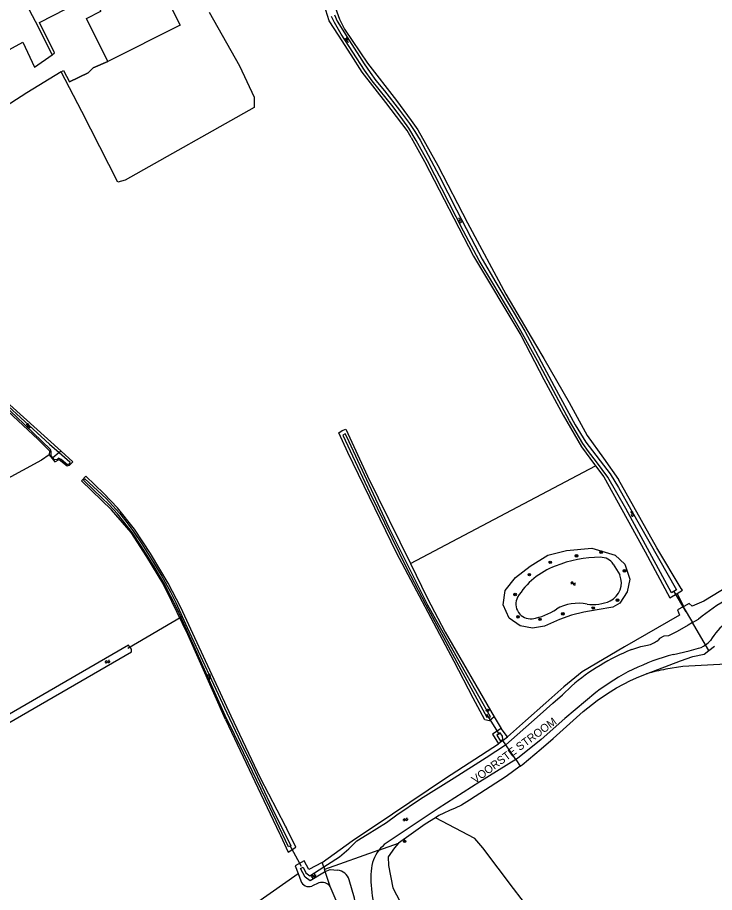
# Model space of a CAD drawing. Extents: x 135999 to 138000, y 396000 to 398501.
# Drawn here: x 136877 to 137094.8, y 396708.1 to 396981.4 of the extents above; entities that cross this region are included whole.
import ezdxf

# ---------------------------------------------------------------- set-up
doc = ezdxf.new("R2010")
doc.units = 0
for name, color, linetype in [('gg-afsc-lijn draadraster', 7, 'Continuous'), ('gg-afsc-muur', 7, 'Continuous'), ('gg-anno-naam water', 7, 'Continuous'), ('gg-bbg-bijgebouw', 7, 'Continuous'), ('gg-knt-BGT kruinlijn', 7, 'Continuous'), ('gg-knt-bronhoudergrens', 7, 'Continuous'), ('gg-kntw-bovenkant insteek waterloop', 7, 'Continuous'), ('gg-kntw-waterlijn', 7, 'Continuous'), ('gg-kwrk-duiker nz buis', 7, 'Continuous'), ('gt-grn-groengrens', 7, 'Continuous'), ('gt-grn-vlakafsluiter', 7, 'Continuous'), ('gt-symb-boom', 7, 'Continuous'), ('gt-symb-watersymbool', 7, 'Continuous'), ('gx-grn-maaiveld', 7, 'Continuous')]:
    doc.layers.add(name, color=color, linetype=linetype)

# ---------------------------------------------------------------- blocks, each defined once
blk = doc.blocks.new('gt0-WA')
at = {"layer": 'gt-symb-watersymbool'}
for centre, start, end in [((-0.32, 0.02), 28.0725, 151.9275), ((0.43, 0.42), 208.0725, 331.9275), ((-0.32, -0.43), 28.0725, 151.9275), ((0.43, -0.03), 208.0725, 331.9275)]:
    blk.add_arc(centre, 0.425, start, end, dxfattribs=at)
blk = doc.blocks.new('gt0-BOOM')
at = {"layer": 'gt-symb-boom'}
for radius in [0.4, 0.2]:
    blk.add_circle((0, 0), radius, dxfattribs=at)

msp = doc.modelspace()

# ---------------------------------------------------------------- linework, layer by layer
at = {"layer": 'gg-afsc-lijn draadraster'}
msp.add_line((136883.71, 396978.2), (136862.33, 397018.93), dxfattribs=at)
at = {"layer": 'gg-afsc-muur'}
for points in [[(136883.88, 396979.86), (136900.29, 396988.38), (136903.04, 396983.36)], [(136905.27, 396967.71), (136900.68, 396965.73), (136899.04, 396964.11), (136893.21, 396961.29)]]:
    msp.add_lwpolyline(points, dxfattribs=at)
at = {"layer": 'gg-bbg-bijgebouw'}
for points in [[(136921.08, 396992.42), (136927.81, 396979.02), (136905.27, 396967.71)], [(136905.27, 396967.71), (136898.54, 396981.1), (136903.04, 396983.36)]]:
    msp.add_lwpolyline(points, dxfattribs=at)
at = {"layer": 'gg-knt-BGT kruinlijn'}
msp.add_lwpolyline([(137098.27, 396779.44), (137084.85, 396778.7), (137079.55, 396777.84)], dxfattribs=at)
msp.add_arc((137087.1, 396734.1), 44.39, 99.788, 107.7671, dxfattribs=at)
at = {"layer": 'gg-knt-bronhoudergrens'}
for p, q in [((137085.17, 396797.45), (137083.11, 396801.55)), ((137025.93, 396763.03), (137028.11, 396759.34)), ((136935.91, 396693.85), (136964.64, 396714.1))]:
    msp.add_line(p, q, dxfattribs=at)
msp.add_lwpolyline([(137042.66, 396813.49), (137048.53, 396814.95), (137056.41, 396815.62), (137063.71, 396813.53), (137066.79, 396810.63), (137068.29, 396806.01), (137067.49, 396802), (137065.22, 396798.53), (137062.95, 396797.2), (137058.14, 396796.4), (137053.91, 396795.66), (137050.11, 396794.76), (137046.3, 396793.4), (137041.67, 396791.31), (137037.95, 396790.67), (137034.05, 396791.4), (137030.6, 396793.85), (137028.7, 396798.02), (137029.31, 396802.41), (137032.64, 396806.54), (137037.18, 396810.01), (137042.66, 396813.49)], dxfattribs=at)
at = {"layer": 'gg-kntw-bovenkant insteek waterloop'}
for p, q in [((137057.31, 396841.77), (137057.58, 396841.41)), ((137057.58, 396841.41), (137060.14, 396837.98)), ((136897.01, 396836.68), (136898.4, 396838.16)), ((137084.73, 396802.52), (137084.37, 396803.11)), ((137080.77, 396800.15), (137083.11, 396801.55)), ((137083.11, 396801.55), (137084.73, 396802.52)), ((137086.89, 396798.42), (137085.17, 396797.45)), ((136941.99, 396762.13), (136953.03, 396738.86)), ((137028.11, 396759.34), (137025.39, 396757.62)), ((137030.07, 396756.7), (137028.11, 396759.34)), ((137025.39, 396757.62), (137027.26, 396754.54)), ((136953.03, 396738.86), (136958.88, 396726.6)), ((136958.88, 396726.6), (136959, 396726.35)), ((136961.19, 396728.04), (136961.07, 396728.29)), ((136963.98, 396722.24), (136961.19, 396728.04)), ((136961.52, 396720.76), (136963.98, 396722.24)), ((136966.53, 396717.97), (136963.77, 396716.43)), ((136963.77, 396716.43), (136964.64, 396714.1)), ((136964.64, 396714.1), (136965.5, 396711.77)), ((136971.17, 396711.11), (136968.95, 396710.12))]:
    msp.add_line(p, q, dxfattribs=at)
for points in [[(137000, 396949.24), (137002.11, 396946.35), (137008.33, 396935.2), (137017.63, 396917.31), (137029.58, 396894.99), (137038.84, 396879.29)], [(137000, 396943.89), (137004.18, 396936.44), (137019.43, 396906.91), (137034.24, 396882.21), (137041.47, 396868.4), (137047.5, 396857.24), (137053.17, 396847.33), (137057.31, 396841.77)], [(137038.84, 396879.29), (137041.42, 396874.91), (137049.34, 396861.13), (137054.93, 396850.82), (137060.06, 396843.8), (137064.81, 396837.1)], [(136864.99, 396866.77), (136875.55, 396856.99), (136883.5, 396849.62), (136887.04, 396846.03), (136886.91, 396844.82)], [(136977.42, 396851.68), (136978.39, 396852.44), (136979.53, 396852.82), (136986.39, 396838.17), (136999.8, 396810.85)], [(137019.4, 396768.84), (137013.38, 396780.26), (136995.44, 396814.21), (136980.24, 396845.59), (136977.42, 396851.68)], [(136888.65, 396842.61), (136890.06, 396843.37), (136892.51, 396841.36)], [(136892.51, 396841.36), (136893.25, 396841.56), (136894.32, 396842.66)], [(136941.99, 396762.13), (136930.19, 396788.66), (136925.25, 396799), (136922.41, 396804.69), (136917.44, 396812.98), (136912.54, 396820.53), (136906.39, 396827.62), (136897.01, 396836.68)], [(136943.79, 396763.16), (136931.75, 396789.01), (136927.98, 396797.11), (136924.06, 396804.77), (136918.52, 396813.99), (136913.59, 396821.57), (136908.29, 396828.23), (136903.99, 396832.71), (136898.4, 396838.16)], [(137060.14, 396837.98), (137073.15, 396814.56), (137080.77, 396800.15)], [(137084.37, 396803.11), (137076.71, 396815.81), (137064.81, 396837.1)], [(136999.8, 396810.85), (137005.03, 396800.19), (137010.65, 396789.47), (137025.93, 396763.03)], [(137102.07, 396805.56), (137091.45, 396799.13), (137087.78, 396797.54), (137086.89, 396798.42)], [(137083.22, 396796.36), (137083.87, 396794.77), (137066.64, 396784.83), (137053.38, 396777.05), (137047.73, 396772.4), (137042.11, 396767.41), (137035.75, 396761.71), (137030.07, 396756.7)], [(136731.41, 396678.55), (136822, 396730.93), (136912.6, 396783.32), (136912.62, 396784.12), (136911.68, 396785.34), (136820.87, 396732.81), (136730.07, 396680.27), (136730.6, 396679.35), (136731.41, 396678.55)], [(137025.93, 396763.03), (137024.49, 396761.69), (137022.98, 396762.07), (137019.4, 396768.84)], [(136961.07, 396728.29), (136960.78, 396728.89), (136952.96, 396743.86), (136943.79, 396763.16)], [(137011.95, 396733.7), (137010.15, 396732.9), (137008.65, 396732.13), (137007.55, 396731.44)], [(137007.55, 396731.44), (137004.4, 396729.48), (137000, 396726.32), (136995.99, 396723.48)], [(136959, 396726.35), (136959.19, 396725.95), (136961.52, 396720.76)], [(136995.99, 396723.48), (136994.8, 396722.05), (136992.85, 396719.25), (136992.93, 396716.57), (136994.31, 396709.6), (136999.87, 396698.88), (137000.79, 396691.21)], [(136975.69, 396674.93), (136977.46, 396676.87), (136978.93, 396681.13), (136978.86, 396694.34), (136976.85, 396704.9), (136974.7, 396710.03)]]:
    msp.add_lwpolyline(points, dxfattribs=at)
for centre, radius, start, end in [((136968.02, 396712.61), 2.66, 198.3459, 290.4131), ((136972.17, 396708.07), 3.2, 37.8692, 108.3403)]:
    msp.add_arc(centre, radius, start, end, dxfattribs=at)
at = {"layer": 'gg-kntw-waterlijn'}
for p, q in [((137063.14, 396810.66), (137065.18, 396807.3)), ((137026.71, 396757.29), (137027.89, 396755.34))]:
    msp.add_line(p, q, dxfattribs=at)
for points in [[(136978.66, 396850.95), (136987.06, 396833), (136998.57, 396809.51), (137004.59, 396797.92), (137014.26, 396780.09), (137023.61, 396762.86), (137024.77, 396763.03), (137017.47, 396775.92), (137005.24, 396797.84), (137000.56, 396807.2), (136993.16, 396822.01), (136979.85, 396850.42), (136979.38, 396851.43), (136978.66, 396850.95)], [(136961.72, 396722.35), (136955.8, 396734.7), (136947.75, 396751.51), (136941.91, 396763.39), (136927.07, 396796.34), (136922.68, 396804.88), (136919.66, 396809.99), (136915.56, 396816.48), (136912.89, 396820.46), (136908.24, 396826.36), (136905.65, 396829.16), (136900.86, 396833.8), (136897.62, 396836.93), (136898.02, 396837.35), (136904.66, 396831.15), (136908.83, 396826.56), (136911.54, 396823.17), (136913.28, 396820.83), (136915.82, 396817.06), (136919.51, 396811.16), (136922.12, 396806.93), (136924.83, 396802), (136926.49, 396798.66), (136930.05, 396790.86), (136942.45, 396764.2), (136946.73, 396755), (136950.39, 396747.54), (136956.46, 396734.67), (136962.38, 396722.74), (136961.72, 396722.35)], [(137068.91, 396783.99), (137071.72, 396784.94), (137073.85, 396785.35)], [(137081.98, 396782.47), (137086.85, 396783.65), (137089.02, 396784.18)], [(137027.89, 396755.34), (137028.64, 396756.05), (137028.57, 396756.98), (137027.83, 396758.03), (137026.71, 396757.29)], [(136982.28, 396681.64), (136982.57, 396686.06), (136983.08, 396701), (136982.28, 396706.39), (136980.66, 396712.05)]]:
    msp.add_lwpolyline(points, dxfattribs=at)
for centre, radius, start, end in [((137059.04, 396775.64), 37.18, 89.893, 112.1587), ((137059.23, 396808.19), 4.63, 32.276, 91.4773), ((137053.51, 396787.79), 23.85, 110.8677, 148.1946), ((137059.32, 396804.88), 6.35, 296.3827, 22.4557), ((137037.3, 396798.2), 4.6, 152.0701, 276.6221), ((137052.21, 396784.74), 13.72, 78.5395, 119.8696), ((137056.78, 396811.29), 13.23, 262.0091, 293.9011), ((137126.31, 396749.51), 57.19, 118.2588, 129.7064), ((137034.94, 396811.91), 18.5, 279.0091, 304.3578), ((137112.32, 396775.21), 22.13, 108.1738, 148.4196), ((137071.57, 396794.38), 9.31, 284.2017, 306.6843), ((137094.28, 396720.69), 68.2, 111.8367, 130.4359), ((137098.76, 396717.52), 67.08, 104.4828, 127.7198), ((136976.61, 396710.83), 4.23, 16.8248, 85.3676), ((137018.3, 396712.29), 30.9, 175.2981, 208.3557)]:
    msp.add_arc(centre, radius, start, end, dxfattribs=at)
at = {"layer": 'gg-kwrk-duiker nz buis'}
for p, q in [((137082.05, 396802.15), (137085.81, 396795.81)), ((136911.46, 396784.45), (136928.3, 396794.28)), ((137023.56, 396763.82), (137027.48, 396757.43)), ((136965.77, 396716.28), (136962.16, 396722.69))]:
    msp.add_line(p, q, dxfattribs=at)
at = {"layer": 'gt-grn-groengrens'}
msp.add_line((136999.8, 396810.85), (137057.58, 396841.41), dxfattribs=at)
msp.add_lwpolyline([(137012.5, 396666.03), (137044.67, 396690.76), (137043.15, 396693.73), (137039.16, 396699.99), (137031.95, 396709.34), (137022.35, 396722.07), (137019.89, 396725), (137007.55, 396731.44)], dxfattribs=at)
at = {"layer": 'gt-grn-vlakafsluiter'}
msp.add_lwpolyline([(136886.91, 396844.82), (136884.46, 396843.11), (136872.6, 396836.66)], dxfattribs=at)
at = {"layer": 'gx-grn-maaiveld'}
for p, q in [((136883.71, 396978.2), (136862.33, 397018.93)), ((136887.84, 396969.81), (136883.71, 396978.2)), ((136886.91, 396844.82), (136887.78, 396843.71)), ((136887.78, 396843.71), (136888.04, 396843.92)), ((136890.03, 396845.54), (136888.04, 396843.92)), ((136890.61, 396846), (136890.03, 396845.54)), ((136890.61, 396846), (136894.32, 396842.66)), ((136887.78, 396843.71), (136888.65, 396842.61)), ((137084.99, 396797.35), (137083.22, 396796.36)), ((137085.17, 396797.45), (137084.99, 396797.35)), ((137084.99, 396797.35), (137087.91, 396792.42)), ((137087.91, 396792.42), (137089.77, 396793.51)), ((137092, 396785.49), (137087.91, 396792.42)), ((137093.04, 396783.73), (137092, 396785.49)), ((137093.04, 396783.73), (137094.77, 396785.05)), ((137028.67, 396755.63), (137027.26, 396754.54)), ((137029.57, 396754.27), (137028.67, 396755.63)), ((137032.65, 396749.63), (137029.57, 396754.27)), ((137032.65, 396749.63), (137034.02, 396747.58)), ((136989.94, 396721.35), (136995.99, 396723.48)), ((136989.94, 396721.35), (136972.93, 396715.34)), ((136968.38, 396713.36), (136972.68, 396716.11)), ((136972.68, 396716.11), (136972.2, 396717.54)), ((136972.68, 396716.11), (136972.93, 396715.34)), ((136973.17, 396714.65), (136972.93, 396715.34)), ((136974.7, 396710.03), (136973.17, 396714.65))]:
    msp.add_line(p, q, dxfattribs=at)
for points in [[(137000, 396943.89), (136998.72, 396946.17), (136992.04, 396954.86), (136984.64, 396964.39), (136981.25, 396969.76), (136977.24, 396975.86), (136974.38, 396980.38), (136972.85, 396985.36), (136971.89, 396990.65), (136970.75, 396997.59), (136970.06, 397000)], [(136972.61, 397000), (136974.25, 396993.89), (136975.34, 396988.01), (136976.4, 396984.38), (136977.65, 396980.94), (136979.18, 396977.81), (136986.35, 396967.11), (136995.41, 396955.52), (137000, 396949.24)], [(136887.84, 396969.81), (136888.6, 396970.35), (136883.88, 396979.86), (136900.29, 396988.38), (136903.04, 396983.36)], [(136936.85, 396983.11), (136946.39, 396966.31), (136950.91, 396956.5), (136950.94, 396953.26), (136910.62, 396930.6), (136908.33, 396930), (136897.08, 396952.02), (136890.62, 396964.4)], [(137081.28, 396801.7), (137067.1, 396828.01), (137061.46, 396837.89), (137057.9, 396842.63), (137055.45, 396845.91), (137053.62, 396848.35), (137049.41, 396855.48), (137039.44, 396874.21), (137034.28, 396883.6), (137031.4, 396888.4), (137025.52, 396898.44), (137021.22, 396905.53), (137016.39, 396914.72), (137005.08, 396936.63), (137001.59, 396943.04), (136999.3, 396946.82), (136997.34, 396949.48), (136994.4, 396953.48), (136987.86, 396961.64), (136985.43, 396964.97), (136978.16, 396976.23), (136976, 396979.86), (136975.11, 396981.77)], [(136976.04, 396982.28), (136976.91, 396980.31), (136980.75, 396974.11), (136985.32, 396966.91), (136987.15, 396964.24), (136988.94, 396961.77), (136991.62, 396958.47), (136996.33, 396952.51), (136999.44, 396948.36), (137001.15, 396945.83), (137002.8, 396943.07), (137008.79, 396931.92), (137014.2, 396921.36), (137018.77, 396912.46), (137022.14, 396905.9), (137026.43, 396898.65), (137031.82, 396889.56), (137035.47, 396883.4), (137037.86, 396878.94), (137040.58, 396873.84), (137044.64, 396866.23), (137051.27, 396854.21), (137054.59, 396848.81), (137062.12, 396838.92), (137064.72, 396834.62), (137068.62, 396827.7), (137082.92, 396802.66), (137081.28, 396801.7)], [(136858.3, 396962.57), (136878.62, 396973.67), (136882.31, 396965.86), (136887.84, 396969.81)], [(136890.62, 396964.4), (136891.39, 396964.87), (136893.21, 396961.29), (136899.04, 396964.11), (136900.68, 396965.73), (136905.27, 396967.71)], [(136890.62, 396964.4), (136879.87, 396957.84), (136865.13, 396948.46), (136864.32, 396949.25)], [(136888.04, 396843.92), (136887.55, 396844.48), (136887.55, 396845.72), (136887.32, 396846.48), (136876.62, 396856.83), (136865.85, 396866.67), (136866.28, 396867.14), (136887.03, 396848.17), (136890.03, 396845.54)], [(136866.14, 396868.05), (136874.63, 396860.41), (136890.61, 396846)], [(136890.03, 396845.54), (136893.3, 396842.68), (136893.2, 396841.97), (136892.67, 396841.74), (136890.65, 396843.41), (136889.85, 396843.77), (136889.37, 396843.36), (136888.58, 396843.29), (136888.04, 396843.92)], [(137087.91, 396792.42), (137086.51, 396791.61), (137083.06, 396789.67), (137080.36, 396788.33), (137078.89, 396788.22), (137077.59, 396787.49), (137077.13, 396786.91)], [(137073.55, 396776.37), (137084.15, 396780.44), (137088.01, 396781.87), (137091.49, 396782.54), (137093.04, 396783.73)], [(137034.02, 396747.58), (137034.63, 396748.02), (137040.62, 396752.99), (137044.4, 396756.26), (137053.69, 396764.63), (137058.07, 396768.12), (137061.29, 396770.32), (137064.13, 396772.02), (137068.5, 396774.38), (137071.12, 396775.51), (137073.55, 396776.37)], [(137029.57, 396754.27), (137033.16, 396757.37), (137040.32, 396763.75), (137044.3, 396767.21), (137047.3, 396769.88), (137050.05, 396772.6)], [(137057.71, 396770.59), (137047.97, 396762.48), (137040.56, 396755.9), (137033.26, 396750.01), (137032.65, 396749.63)], [(137028.67, 396755.63), (137028.69, 396755.65), (137030.07, 396756.7)], [(136972.2, 396717.54), (136981.58, 396724.24), (136994.12, 396732.7), (137010.76, 396743.88), (137027.26, 396754.54)], [(136972.68, 396716.11), (136973.84, 396716.86), (136977.56, 396719.24), (136980.53, 396721.76), (136983.04, 396724.21), (136986.24, 396726.19), (136992.33, 396729.95), (136995.52, 396732.4), (137002.91, 396737.36), (137013.4, 396743.94), (137023.47, 396750.24), (137029.5, 396754.2), (137029.57, 396754.27)], [(137032.65, 396749.63), (137021.44, 396742.68), (137008.4, 396734.38), (136992.23, 396723.57)], [(137034.02, 396747.58), (137029.64, 396744.39), (137018.27, 396736.97), (137015.7, 396735.44), (137013.74, 396734.51), (137011.95, 396733.7)], [(136973.17, 396714.65), (136972.9, 396714.52), (136968.41, 396711.8), (136966.87, 396712.87), (136965.45, 396715.6), (136966.24, 396716.03), (136967.11, 396714.25), (136968.38, 396713.36)], [(136972.2, 396717.54), (136968.02, 396715.33), (136966.53, 396717.97)], [(136973.17, 396714.65), (136974.67, 396715.35), (136976.95, 396715.05)]]:
    msp.add_lwpolyline(points, dxfattribs=at)
for centre, radius, start, end in [((137087.23, 396792.28), 8.3, 305.1142, 318.6821), ((137087.23, 396792.29), 8.3, 282.4472, 305.1032), ((136999.16, 396714.16), 11.69, 126.3597, 142.0671), ((136999.15, 396714.18), 11.67, 142.1081, 176.8145)]:
    msp.add_arc(centre, radius, start, end, dxfattribs=at)

# ---------------------------------------------------------------- block references
at = {"layer": 'gt-symb-boom'}
for p in [(137051.66, 396813.26), (137059.35, 396814.41), (137043.45, 396811.23), (137066.66, 396808.6), (137036.92, 396807.38), (137032.46, 396801.2), (137056.89, 396796.97), (137064.46, 396799.41), (137033.38, 396794.2), (137047.38, 396795.17), (137040.26, 396793.44), (137023.86, 396765.03), (136997.96, 396724.13)]:
    msp.add_blockref('gt0-BOOM', p, dxfattribs=at)
at = {"layer": 'gt-symb-watersymbool'}
for p, rotation in [((136979.84, 396974.3), -56.707151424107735), ((137015.27, 396918.14), -62.69221993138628), ((136880.35, 396853.88), -41.99999127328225), ((137069.01, 396826.43), -60.84518962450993), ((136905.06, 396780.16), 30.050323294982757), ((136936.96, 396775.58), -65.04884837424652), ((136998.27, 396730.91), -144.40236850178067), ((136969.46, 396713.18), 47.06710321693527)]:
    msp.add_blockref('gt0-WA', p, dxfattribs=dict(at, rotation=rotation))
msp.add_blockref('gt0-WA', (137050.58, 396804.65), dxfattribs=at)

# ---------------------------------------------------------------- texts
at = {"layer": 'gg-anno-naam water'}
msp.add_text('VOORSTE STROOM', height=2.5, rotation=36.3771, dxfattribs=at).set_placement((137019.99, 396742.02))

doc.saveas('drawing.dxf')
